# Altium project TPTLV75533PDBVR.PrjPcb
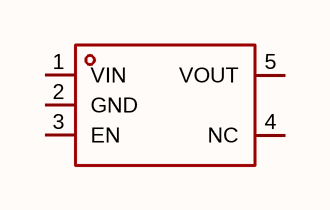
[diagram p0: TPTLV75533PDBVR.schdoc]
1 sheet, 1 parts. Net scope: global (net labels, ports and power ports of the same name join across sheets).

## Sheet TPTLV75533PDBVR.schdoc
size 127 x 101 mm

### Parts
U?  tptlv75533pdbvr  [SOT-23-5_L3.0-W1.7-P0.95-LS2.8-BR]  (value not drawn)

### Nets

Not connected (* = marked no-connect by the designer): U? 1(VIN) 2(GND) 3(EN) 4(NC) 5(VOUT)

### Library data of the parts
U? = tptlv75533pdbvr: 输出极性:正极;工作电压:5.5V;输出电压:3.3V;输出电流:500mA;电源纹波抑制比(PSRR):-;输出类型:固定;; Manufacturer: TECH PUBLIC(台舟); AddInBom: yes; ModelId: 0a2a1b8f50944f73965918ad6e5fe167; ModelName: SOT-23-5_L2.9-W1.6-H1.1-LS2.8-P0.95; ModelTransform: 114.173,109.636,0,180,0,0,0,0,0; Output Configuration: 正极; Voltage - Supply: 5.5V; Output Voltage: 3.3V; Output Current: 500mA; Voltage Dropout: 320mV@(600mA); standby current: 5uA; Output Type: 固定; Number of Outputs: 1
